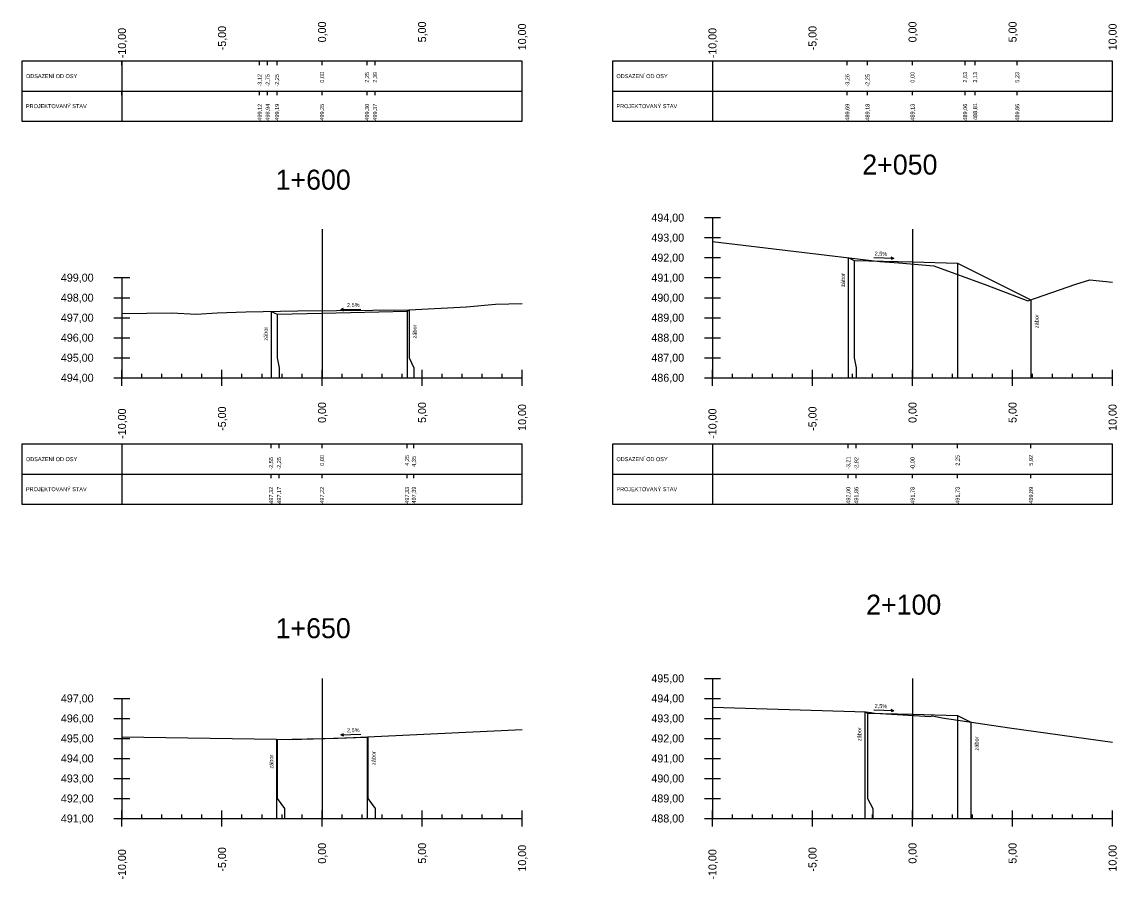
# Model space of a CAD drawing. Extents: x -631407 to -631215, y -1089700 to -1088598.
# Drawn here: x -631314.7 to -631259.9, y -1088900.4 to -1088857.6 of the extents above; entities that cross this region are included whole.
import ezdxf

# ---------------------------------------------------------------- set-up
doc = ezdxf.new("R2010")
doc.units = 0
for name, color, linetype in [('59', 7, 'Continuous'), ('NIVELETA_VYSKY', 7, 'Continuous'), ('REZ_BODY', 7, 'Continuous'), ('REZ_ODSTUPY', 7, 'Continuous'), ('REZ_POPIS', 7, 'Continuous'), ('REZ_RAMY', 7, 'Continuous'), ('REZ_STANICENI', 7, 'Continuous'), ('REZ_SVISLE', 7, 'Continuous'), ('REZ_TENKA', 7, 'Continuous'), ('REZ_TLUSTA', 7, 'Continuous'), ('TABULKA_POPIS', 7, 'Continuous'), ('TEREN', 7, 'Continuous'), ('zábor', 7, 'Continuous')]:
    doc.layers.add(name, color=color, linetype=linetype)

msp = doc.modelspace()

# ---------------------------------------------------------------- linework, layer by layer
at = {"layer": '59'}
for p, q in [((-631280.602, -1088867.359), (-631279.802, -1088867.359)), ((-631280.202, -1088867.359), (-631280.202, -1088875.359)), ((-631280.602, -1088868.359), (-631279.802, -1088868.359)), ((-631280.602, -1088869.359), (-631279.802, -1088869.359)), ((-631310.116, -1088870.359), (-631309.316, -1088870.359)), ((-631309.716, -1088870.359), (-631309.716, -1088875.359)), ((-631280.602, -1088870.359), (-631279.802, -1088870.359)), ((-631310.116, -1088871.359), (-631309.316, -1088871.359)), ((-631280.602, -1088871.359), (-631279.802, -1088871.359)), ((-631310.116, -1088872.359), (-631309.316, -1088872.359)), ((-631280.602, -1088872.359), (-631279.802, -1088872.359)), ((-631310.116, -1088873.359), (-631309.316, -1088873.359)), ((-631280.602, -1088873.359), (-631279.802, -1088873.359)), ((-631310.116, -1088874.359), (-631309.316, -1088874.359)), ((-631280.602, -1088874.359), (-631279.802, -1088874.359)), ((-631310.116, -1088875.359), (-631309.316, -1088875.359)), ((-631280.602, -1088875.359), (-631279.802, -1088875.359)), ((-631280.602, -1088890.381), (-631279.802, -1088890.381)), ((-631280.202, -1088890.381), (-631280.202, -1088897.381)), ((-631310.116, -1088891.381), (-631309.316, -1088891.381)), ((-631309.716, -1088891.381), (-631309.716, -1088897.381)), ((-631280.602, -1088891.381), (-631279.802, -1088891.381)), ((-631310.116, -1088892.381), (-631309.316, -1088892.381)), ((-631280.602, -1088892.381), (-631279.802, -1088892.381)), ((-631310.116, -1088893.381), (-631309.316, -1088893.381)), ((-631280.602, -1088893.381), (-631279.802, -1088893.381)), ((-631310.116, -1088894.381), (-631309.316, -1088894.381)), ((-631280.602, -1088894.381), (-631279.802, -1088894.381)), ((-631310.116, -1088895.381), (-631309.316, -1088895.381)), ((-631280.602, -1088895.381), (-631279.802, -1088895.381)), ((-631310.116, -1088896.381), (-631309.316, -1088896.381)), ((-631280.602, -1088896.381), (-631279.802, -1088896.381)), ((-631310.116, -1088897.381), (-631309.316, -1088897.381)), ((-631280.602, -1088897.381), (-631279.802, -1088897.381))]:
    msp.add_line(p, q, dxfattribs=at)
at = {"layer": 'REZ_RAMY'}
for p, q in [((-631314.716, -1088859.539), (-631314.716, -1088862.539)), ((-631309.716, -1088859.539), (-631309.716, -1088862.539)), ((-631309.716, -1088859.739), (-631309.716, -1088859.539)), ((-631302.833, -1088859.739), (-631302.833, -1088859.539)), ((-631302.433, -1088859.739), (-631302.433, -1088859.539)), ((-631301.966, -1088859.739), (-631301.966, -1088859.539)), ((-631299.716, -1088859.739), (-631299.716, -1088859.539)), ((-631297.466, -1088859.739), (-631297.466, -1088859.539)), ((-631297.066, -1088859.739), (-631297.066, -1088859.539)), ((-631285.202, -1088859.539), (-631285.202, -1088862.539)), ((-631280.202, -1088859.539), (-631280.202, -1088862.539)), ((-631273.461, -1088859.739), (-631273.461, -1088859.539)), ((-631272.452, -1088859.739), (-631272.452, -1088859.539)), ((-631270.202, -1088859.739), (-631270.202, -1088859.539)), ((-631267.571, -1088859.739), (-631267.571, -1088859.539)), ((-631267.071, -1088859.739), (-631267.071, -1088859.539)), ((-631264.969, -1088859.739), (-631264.969, -1088859.539)), ((-631314.716, -1088861.039), (-631289.716, -1088861.039)), ((-631309.716, -1088861.239), (-631309.716, -1088861.039)), ((-631302.833, -1088861.239), (-631302.833, -1088861.039)), ((-631302.433, -1088861.239), (-631302.433, -1088861.039)), ((-631301.966, -1088861.239), (-631301.966, -1088861.039)), ((-631299.716, -1088861.239), (-631299.716, -1088861.039)), ((-631297.466, -1088861.239), (-631297.466, -1088861.039)), ((-631297.066, -1088861.239), (-631297.066, -1088861.039)), ((-631285.202, -1088861.039), (-631260.202, -1088861.039)), ((-631273.461, -1088861.239), (-631273.461, -1088861.039)), ((-631272.452, -1088861.239), (-631272.452, -1088861.039)), ((-631270.202, -1088861.239), (-631270.202, -1088861.039)), ((-631267.571, -1088861.239), (-631267.571, -1088861.039)), ((-631267.071, -1088861.239), (-631267.071, -1088861.039)), ((-631264.969, -1088861.239), (-631264.969, -1088861.039)), ((-631314.716, -1088878.678), (-631314.716, -1088881.678)), ((-631309.716, -1088878.678), (-631309.716, -1088881.678)), ((-631302.261, -1088878.878), (-631302.261, -1088878.678)), ((-631301.861, -1088878.878), (-631301.861, -1088878.678)), ((-631299.716, -1088878.878), (-631299.716, -1088878.678)), ((-631295.466, -1088878.878), (-631295.466, -1088878.678)), ((-631295.127, -1088878.878), (-631295.127, -1088878.678)), ((-631285.202, -1088878.678), (-631285.202, -1088881.678)), ((-631280.202, -1088878.678), (-631280.202, -1088881.678)), ((-631273.412, -1088878.878), (-631273.412, -1088878.678)), ((-631273.012, -1088878.878), (-631273.012, -1088878.678)), ((-631270.202, -1088878.878), (-631270.202, -1088878.678)), ((-631267.952, -1088878.878), (-631267.952, -1088878.678)), ((-631264.281, -1088878.878), (-631264.281, -1088878.678)), ((-631314.716, -1088880.178), (-631289.716, -1088880.178)), ((-631302.261, -1088880.378), (-631302.261, -1088880.178)), ((-631301.861, -1088880.378), (-631301.861, -1088880.178)), ((-631299.716, -1088880.378), (-631299.716, -1088880.178)), ((-631295.466, -1088880.378), (-631295.466, -1088880.178)), ((-631295.127, -1088880.378), (-631295.127, -1088880.178)), ((-631285.202, -1088880.178), (-631260.202, -1088880.178)), ((-631273.412, -1088880.378), (-631273.412, -1088880.178)), ((-631273.012, -1088880.378), (-631273.012, -1088880.178)), ((-631270.202, -1088880.378), (-631270.202, -1088880.178)), ((-631267.952, -1088880.378), (-631267.952, -1088880.178)), ((-631264.281, -1088880.378), (-631264.281, -1088880.178))]:
    msp.add_line(p, q, dxfattribs=at)
for points in [[(-631314.716, -1088859.539), (-631314.716, -1088862.539), (-631289.716, -1088862.539), (-631289.716, -1088859.539)], [(-631285.202, -1088859.539), (-631285.202, -1088862.539), (-631260.202, -1088862.539), (-631260.202, -1088859.539)], [(-631314.716, -1088878.678), (-631314.716, -1088881.678), (-631289.716, -1088881.678), (-631289.716, -1088878.678)], [(-631285.202, -1088878.678), (-631285.202, -1088881.678), (-631260.202, -1088881.678), (-631260.202, -1088878.678)]]:
    msp.add_lwpolyline(points, close=True, dxfattribs=at)
at = {"layer": 'REZ_SVISLE'}
for points in [[(-631273.412, -1088869.357), (-631273.412, -1088874.359), (-631273.412, -1088874.859), (-631273.412, -1088875.359)], [(-631273.122, -1088869.502), (-631273.122, -1088874.359), (-631273.012, -1088874.859), (-631273.012, -1088875.359)], [(-631270.202, -1088869.575), (-631270.202, -1088874.359), (-631270.202, -1088874.859), (-631270.202, -1088875.359)], [(-631267.952, -1088869.631), (-631267.952, -1088874.359), (-631267.952, -1088874.859), (-631267.952, -1088875.359)], [(-631264.281, -1088871.467), (-631264.281, -1088874.359), (-631264.281, -1088874.859), (-631264.281, -1088875.359)], [(-631302.261, -1088872.043), (-631302.261, -1088874.359), (-631302.261, -1088874.859), (-631302.261, -1088875.359)], [(-631301.966, -1088872.191), (-631301.966, -1088874.359), (-631301.861, -1088874.859), (-631301.861, -1088875.359)], [(-631299.716, -1088872.135), (-631299.716, -1088874.359), (-631299.716, -1088874.859), (-631299.716, -1088875.359)], [(-631295.466, -1088872.028), (-631295.466, -1088874.359), (-631295.466, -1088874.859), (-631295.466, -1088875.359)], [(-631295.365, -1088871.968), (-631295.365, -1088874.359), (-631295.127, -1088874.859), (-631295.127, -1088875.359)], [(-631272.586, -1088892.053), (-631272.586, -1088896.381), (-631272.586, -1088896.881), (-631272.586, -1088897.381)], [(-631272.452, -1088892.12), (-631272.452, -1088896.381), (-631272.186, -1088896.881), (-631272.186, -1088897.381)], [(-631270.202, -1088892.176), (-631270.202, -1088896.381), (-631270.202, -1088896.881), (-631270.202, -1088897.381)], [(-631267.952, -1088892.232), (-631267.952, -1088896.381), (-631267.952, -1088896.881), (-631267.952, -1088897.381)], [(-631267.283, -1088892.567), (-631267.283, -1088896.381), (-631267.283, -1088896.881), (-631267.283, -1088897.381)], [(-631301.984, -1088893.425), (-631301.984, -1088896.381), (-631301.984, -1088896.881), (-631301.984, -1088897.381)], [(-631301.966, -1088893.434), (-631301.966, -1088896.381), (-631301.584, -1088896.881), (-631301.584, -1088897.381)], [(-631299.716, -1088893.378), (-631299.716, -1088896.381), (-631299.716, -1088896.881), (-631299.716, -1088897.381)], [(-631297.466, -1088893.321), (-631297.466, -1088896.381), (-631297.466, -1088896.881), (-631297.466, -1088897.381)], [(-631297.422, -1088893.295), (-631297.422, -1088896.381), (-631297.066, -1088896.881), (-631297.066, -1088897.381)]]:
    msp.add_lwpolyline(points, dxfattribs=at)
at = {"layer": 'REZ_TENKA'}
for p, q in [((-631308.716, -1088875.359), (-631308.716, -1088875.159)), ((-631307.716, -1088875.359), (-631307.716, -1088875.159)), ((-631306.716, -1088875.359), (-631306.716, -1088875.159)), ((-631305.716, -1088875.359), (-631305.716, -1088875.159)), ((-631303.716, -1088875.359), (-631303.716, -1088875.159)), ((-631302.716, -1088875.359), (-631302.716, -1088875.159)), ((-631301.716, -1088875.359), (-631301.716, -1088875.159)), ((-631300.716, -1088875.359), (-631300.716, -1088875.159)), ((-631298.716, -1088875.359), (-631298.716, -1088875.159)), ((-631297.716, -1088875.359), (-631297.716, -1088875.159)), ((-631296.716, -1088875.359), (-631296.716, -1088875.159)), ((-631295.716, -1088875.359), (-631295.716, -1088875.159)), ((-631293.716, -1088875.359), (-631293.716, -1088875.159)), ((-631292.716, -1088875.359), (-631292.716, -1088875.159)), ((-631291.716, -1088875.359), (-631291.716, -1088875.159)), ((-631290.716, -1088875.359), (-631290.716, -1088875.159)), ((-631279.202, -1088875.359), (-631279.202, -1088875.159)), ((-631278.202, -1088875.359), (-631278.202, -1088875.159)), ((-631277.202, -1088875.359), (-631277.202, -1088875.159)), ((-631276.202, -1088875.359), (-631276.202, -1088875.159)), ((-631274.202, -1088875.359), (-631274.202, -1088875.159)), ((-631273.202, -1088875.359), (-631273.202, -1088875.159)), ((-631272.202, -1088875.359), (-631272.202, -1088875.159)), ((-631271.202, -1088875.359), (-631271.202, -1088875.159)), ((-631269.202, -1088875.359), (-631269.202, -1088875.159)), ((-631268.202, -1088875.359), (-631268.202, -1088875.159)), ((-631267.202, -1088875.359), (-631267.202, -1088875.159)), ((-631266.202, -1088875.359), (-631266.202, -1088875.159)), ((-631264.202, -1088875.359), (-631264.202, -1088875.159)), ((-631263.202, -1088875.359), (-631263.202, -1088875.159)), ((-631262.202, -1088875.359), (-631262.202, -1088875.159)), ((-631261.202, -1088875.359), (-631261.202, -1088875.159)), ((-631308.716, -1088897.381), (-631308.716, -1088897.181)), ((-631307.716, -1088897.381), (-631307.716, -1088897.181)), ((-631306.716, -1088897.381), (-631306.716, -1088897.181)), ((-631305.716, -1088897.381), (-631305.716, -1088897.181)), ((-631303.716, -1088897.381), (-631303.716, -1088897.181)), ((-631302.716, -1088897.381), (-631302.716, -1088897.181)), ((-631301.716, -1088897.381), (-631301.716, -1088897.181)), ((-631300.716, -1088897.381), (-631300.716, -1088897.181)), ((-631298.716, -1088897.381), (-631298.716, -1088897.181)), ((-631297.716, -1088897.381), (-631297.716, -1088897.181)), ((-631296.716, -1088897.381), (-631296.716, -1088897.181)), ((-631295.716, -1088897.381), (-631295.716, -1088897.181)), ((-631293.716, -1088897.381), (-631293.716, -1088897.181)), ((-631292.716, -1088897.381), (-631292.716, -1088897.181)), ((-631291.716, -1088897.381), (-631291.716, -1088897.181)), ((-631290.716, -1088897.381), (-631290.716, -1088897.181)), ((-631279.202, -1088897.381), (-631279.202, -1088897.181)), ((-631278.202, -1088897.381), (-631278.202, -1088897.181)), ((-631277.202, -1088897.381), (-631277.202, -1088897.181)), ((-631276.202, -1088897.381), (-631276.202, -1088897.181)), ((-631274.202, -1088897.381), (-631274.202, -1088897.181)), ((-631273.202, -1088897.381), (-631273.202, -1088897.181)), ((-631272.202, -1088897.381), (-631272.202, -1088897.181)), ((-631271.202, -1088897.381), (-631271.202, -1088897.181)), ((-631269.202, -1088897.381), (-631269.202, -1088897.181)), ((-631268.202, -1088897.381), (-631268.202, -1088897.181)), ((-631267.202, -1088897.381), (-631267.202, -1088897.181)), ((-631266.202, -1088897.381), (-631266.202, -1088897.181)), ((-631264.202, -1088897.381), (-631264.202, -1088897.181)), ((-631263.202, -1088897.381), (-631263.202, -1088897.181)), ((-631262.202, -1088897.381), (-631262.202, -1088897.181)), ((-631261.202, -1088897.381), (-631261.202, -1088897.181))]:
    msp.add_line(p, q, dxfattribs=at)
at = {"layer": 'REZ_TLUSTA'}
for p, q in [((-631299.716, -1088867.939), (-631299.716, -1088875.359)), ((-631270.202, -1088867.939), (-631270.202, -1088875.359)), ((-631309.716, -1088875.759), (-631309.716, -1088874.959)), ((-631304.716, -1088875.759), (-631304.716, -1088874.959)), ((-631299.716, -1088875.759), (-631299.716, -1088874.959)), ((-631294.716, -1088875.759), (-631294.716, -1088874.959)), ((-631289.716, -1088875.759), (-631289.716, -1088874.959)), ((-631280.202, -1088875.759), (-631280.202, -1088874.959)), ((-631275.202, -1088875.759), (-631275.202, -1088874.959)), ((-631270.202, -1088875.759), (-631270.202, -1088874.959)), ((-631265.202, -1088875.759), (-631265.202, -1088874.959)), ((-631260.202, -1088875.759), (-631260.202, -1088874.959)), ((-631309.716, -1088875.359), (-631289.716, -1088875.359)), ((-631280.202, -1088875.359), (-631260.202, -1088875.359)), ((-631299.716, -1088890.381), (-631299.716, -1088897.381)), ((-631270.202, -1088890.381), (-631270.202, -1088897.381)), ((-631309.716, -1088897.781), (-631309.716, -1088896.981)), ((-631304.716, -1088897.781), (-631304.716, -1088896.981)), ((-631299.716, -1088897.781), (-631299.716, -1088896.981)), ((-631294.716, -1088897.781), (-631294.716, -1088896.981)), ((-631289.716, -1088897.781), (-631289.716, -1088896.981)), ((-631280.202, -1088897.781), (-631280.202, -1088896.981)), ((-631275.202, -1088897.781), (-631275.202, -1088896.981)), ((-631270.202, -1088897.781), (-631270.202, -1088896.981)), ((-631265.202, -1088897.781), (-631265.202, -1088896.981)), ((-631260.202, -1088897.781), (-631260.202, -1088896.981)), ((-631309.716, -1088897.381), (-631289.716, -1088897.381)), ((-631280.202, -1088897.381), (-631260.202, -1088897.381))]:
    msp.add_line(p, q, dxfattribs=at)
at = {"layer": 'TEREN'}
for points in [[(-631280.202, -1088868.554), (-631271.836, -1088869.544), (-631270.885, -1088869.613), (-631269.13, -1088869.774), (-631266.493, -1088870.726), (-631264.43, -1088871.519), (-631262.041, -1088870.69), (-631261.333, -1088870.466), (-631260.202, -1088870.591)], [(-631273.412, -1088869.357), (-631273.122, -1088869.502), (-631270.202, -1088869.575), (-631267.952, -1088869.631), (-631264.281, -1088871.467)], [(-631309.716, -1088872.15), (-631307.218, -1088872.116), (-631306.003, -1088872.175), (-631304.954, -1088872.113), (-631303.52, -1088872.063), (-631300.931, -1088872.023), (-631298.988, -1088871.993), (-631295.362, -1088871.968), (-631292.493, -1088871.817), (-631291.045, -1088871.679), (-631289.716, -1088871.652)], [(-631302.261, -1088872.043), (-631301.966, -1088872.191), (-631299.716, -1088872.135), (-631295.466, -1088872.028), (-631295.365, -1088871.968)], [(-631280.202, -1088891.823), (-631272.532, -1088892.054), (-631272.269, -1088892.084), (-631272.208, -1088892.102), (-631272.078, -1088892.113), (-631269.296, -1088892.282), (-631269.225, -1088892.26), (-631268.713, -1088892.36), (-631265.358, -1088892.846), (-631260.202, -1088893.569)], [(-631272.586, -1088892.053), (-631272.452, -1088892.12), (-631270.202, -1088892.176), (-631267.952, -1088892.232), (-631267.283, -1088892.567)], [(-631309.716, -1088893.298), (-631302.002, -1088893.425), (-631301.336, -1088893.433), (-631298.964, -1088893.363), (-631298.923, -1088893.361), (-631298.49, -1088893.344), (-631289.716, -1088892.942)], [(-631301.984, -1088893.425), (-631301.966, -1088893.434), (-631299.716, -1088893.378), (-631297.466, -1088893.321), (-631297.422, -1088893.295)]]:
    msp.add_lwpolyline(points, dxfattribs=at)
at = {"layer": 'zábor'}
for p, q in [((-631271.135, -1088869.396), (-631272.143, -1088869.37)), ((-631271.135, -1088869.396), (-631271.274, -1088869.453)), ((-631271.135, -1088869.396), (-631271.271, -1088869.331)), ((-631298.783, -1088871.955), (-631298.646, -1088871.89)), ((-631298.783, -1088871.955), (-631297.775, -1088871.93)), ((-631298.783, -1088871.955), (-631298.643, -1088872.013)), ((-631271.135, -1088891.997), (-631272.143, -1088891.971)), ((-631271.135, -1088891.997), (-631271.274, -1088892.054)), ((-631271.135, -1088891.997), (-631271.271, -1088891.932)), ((-631298.783, -1088893.198), (-631298.646, -1088893.134)), ((-631298.783, -1088893.198), (-631297.775, -1088893.173)), ((-631298.783, -1088893.198), (-631298.643, -1088893.256))]:
    msp.add_line(p, q, dxfattribs=at)

# ---------------------------------------------------------------- texts
at = {"layer": 'NIVELETA_VYSKY'}
for s, p in [('499,12', (-631302.733, -1088862.515)), ('498,94', (-631302.333, -1088862.515)), ('499,19', (-631301.866, -1088862.515)), ('499,25', (-631299.616, -1088862.515)), ('499,30', (-631297.366, -1088862.515)), ('499,37', (-631296.966, -1088862.515)), ('489,69', (-631273.361, -1088862.515)), ('489,18', (-631272.352, -1088862.515)), ('489,13', (-631270.102, -1088862.515)), ('489,06', (-631267.471, -1088862.515)), ('488,81', (-631266.971, -1088862.482)), ('489,86', (-631264.869, -1088862.515)), ('497,32', (-631302.161, -1088881.654)), ('497,17', (-631301.761, -1088881.654)), ('497,22', (-631299.616, -1088881.654)), ('497,33', (-631295.366, -1088881.654)), ('497,39', (-631295.027, -1088881.644)), ('492,00', (-631273.312, -1088881.654)), ('491,86', (-631272.912, -1088881.654)), ('491,78', (-631270.102, -1088881.654)), ('491,73', (-631267.852, -1088881.654)), ('489,89', (-631264.181, -1088881.654))]:
    msp.add_text(s, height=0.2, rotation=90, dxfattribs=at).set_placement(p)
at = {"layer": 'REZ_BODY'}
for s, p in [('-3,12', (-631302.733, -1088860.816)), ('-2,75', (-631302.333, -1088860.816)), ('-2,25', (-631301.866, -1088860.816)), ('0,00', (-631299.616, -1088860.618)), ('2,25', (-631297.366, -1088860.618)), ('2,39', (-631296.966, -1088860.618)), ('-3,26', (-631273.361, -1088860.816)), ('-2,25', (-631272.352, -1088860.816)), ('0,00', (-631270.102, -1088860.618)), ('2,63', (-631267.471, -1088860.618)), ('3,13', (-631266.971, -1088860.618)), ('5,23', (-631264.869, -1088860.618)), ('-2,55', (-631302.161, -1088879.955)), ('-2,25', (-631301.761, -1088879.955)), ('0,00', (-631299.616, -1088879.757)), ('4,25', (-631295.366, -1088879.757)), ('4,35', (-631295.027, -1088879.81)), ('-3,21', (-631273.312, -1088879.922)), ('-2,92', (-631272.912, -1088879.955)), ('-0,00', (-631270.102, -1088879.955)), ('2,25', (-631267.852, -1088879.757)), ('5,92', (-631264.181, -1088879.757))]:
    msp.add_text(s, height=0.2, rotation=90, dxfattribs=at).set_placement(p)
at = {"layer": 'REZ_ODSTUPY'}
for s, p in [('0,00', (-631299.516, -1088858.601)), ('5,00', (-631294.516, -1088858.601)), ('0,00', (-631270.002, -1088858.601)), ('5,00', (-631265.002, -1088858.601)), ('-10,00', (-631309.516, -1088859.395)), ('-5,00', (-631304.516, -1088858.998)), ('10,00', (-631289.516, -1088858.998)), ('-10,00', (-631280.002, -1088859.395)), ('-5,00', (-631275.002, -1088858.998)), ('10,00', (-631260.002, -1088858.998)), ('0,00', (-631299.516, -1088877.618)), ('5,00', (-631294.516, -1088877.618)), ('10,00', (-631289.516, -1088878.014)), ('0,00', (-631270.002, -1088877.618)), ('5,00', (-631265.002, -1088877.618)), ('10,00', (-631260.002, -1088878.014)), ('-10,00', (-631309.516, -1088878.411)), ('-5,00', (-631304.516, -1088878.014)), ('-10,00', (-631280.002, -1088878.411)), ('-5,00', (-631275.002, -1088878.014)), ('0,00', (-631299.516, -1088899.639)), ('5,00', (-631294.516, -1088899.639)), ('0,00', (-631270.002, -1088899.639)), ('5,00', (-631265.002, -1088899.639)), ('-10,00', (-631309.516, -1088900.433)), ('-5,00', (-631304.516, -1088900.036)), ('10,00', (-631289.516, -1088900.036)), ('-10,00', (-631280.002, -1088900.433)), ('-5,00', (-631275.002, -1088900.036)), ('10,00', (-631260.002, -1088900.036))]:
    msp.add_text(s, height=0.4, rotation=90, dxfattribs=at).set_placement(p)
at = {"layer": 'REZ_POPIS'}
for s, p in [('494,00', (-631283.254, -1088867.559)), ('493,00', (-631283.254, -1088868.559)), ('492,00', (-631283.254, -1088869.559)), ('499,00', (-631312.768, -1088870.559)), ('491,00', (-631283.254, -1088870.559)), ('498,00', (-631312.768, -1088871.559)), ('490,00', (-631283.254, -1088871.559)), ('497,00', (-631312.768, -1088872.559)), ('489,00', (-631283.254, -1088872.559)), ('496,00', (-631312.768, -1088873.559)), ('488,00', (-631283.254, -1088873.559)), ('495,00', (-631312.768, -1088874.559)), ('487,00', (-631283.254, -1088874.559)), ('494,00', (-631312.768, -1088875.559)), ('486,00', (-631283.254, -1088875.559)), ('495,00', (-631283.254, -1088890.581)), ('497,00', (-631312.768, -1088891.581)), ('494,00', (-631283.254, -1088891.581)), ('496,00', (-631312.768, -1088892.581)), ('493,00', (-631283.254, -1088892.581)), ('495,00', (-631312.768, -1088893.581)), ('492,00', (-631283.254, -1088893.581)), ('494,00', (-631312.768, -1088894.581)), ('491,00', (-631283.254, -1088894.581)), ('493,00', (-631312.768, -1088895.581)), ('490,00', (-631283.254, -1088895.581)), ('492,00', (-631312.768, -1088896.581)), ('489,00', (-631283.254, -1088896.581)), ('491,00', (-631312.768, -1088897.581)), ('488,00', (-631283.254, -1088897.581))]:
    msp.add_text(s, height=0.4, dxfattribs=at).set_placement(p)
at = {"layer": 'REZ_STANICENI'}
for s, p in [('2+050', (-631272.711, -1088865.209)), ('1+600', (-631302.035, -1088865.963)), ('2+100', (-631272.52, -1088887.198)), ('1+650', (-631302.035, -1088888.374))]:
    msp.add_text(s, height=1, dxfattribs=at).set_placement(p)
at = {"layer": 'TABULKA_POPIS'}
for s, p in [('ODSAZENÍ OD OSY', (-631314.516, -1088860.389)), ('ODSAZENÍ OD OSY', (-631285.002, -1088860.389)), ('PROJEKTOVANÝ STAV', (-631314.516, -1088861.889)), ('PROJEKTOVANÝ STAV', (-631285.002, -1088861.889)), ('ODSAZENÍ OD OSY', (-631314.516, -1088879.528)), ('ODSAZENÍ OD OSY', (-631285.002, -1088879.528)), ('PROJEKTOVANÝ STAV', (-631314.516, -1088881.028)), ('PROJEKTOVANÝ STAV', (-631285.002, -1088881.028))]:
    msp.add_text(s, height=0.2, dxfattribs=at).set_placement(p)
at = {"layer": 'zábor'}
for s, rotation, p in [('2,5%', 358.5679, (-631272.099, -1088869.258)), ('zábor', 90, (-631273.582, -1088870.82)), ('2,5%', 1.4321, (-631298.466, -1088871.834)), ('zábor', 90, (-631263.898, -1088872.881)), ('zábor', 90, (-631302.431, -1088873.507)), ('zábor', 90, (-631294.982, -1088873.396)), ('2,5%', 358.5679, (-631272.099, -1088891.859)), ('2,5%', 1.4321, (-631298.466, -1088893.077)), ('zábor', 90, (-631272.757, -1088893.516)), ('zábor', 90, (-631266.9, -1088893.981)), ('zábor', 90, (-631302.154, -1088894.888)), ('zábor', 90, (-631297.039, -1088894.709))]:
    msp.add_text(s, height=0.2, rotation=rotation, dxfattribs=at).set_placement(p)

doc.saveas('drawing.dxf')
